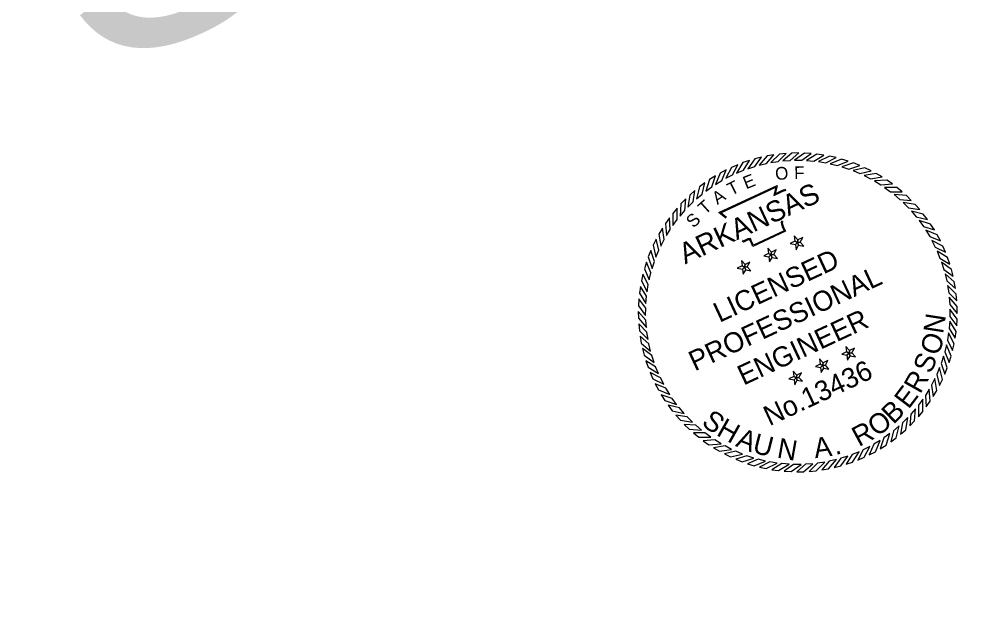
# Model space of a CAD drawing. Extents: x 757022 to 766943, y 1656388 to 1662319.
# Drawn here: x 758834 to 759548, y 1659146 to 1659585 of the extents above; entities that cross this region are included whole.
import ezdxf

# ---------------------------------------------------------------- set-up
doc = ezdxf.new("R2010")
doc.units = 0
doc.layers.add('1', color=7, linetype='Continuous')
doc.layers.add('G-ANNO-SYMB', color=7, linetype='Continuous')

msp = doc.modelspace()

# ---------------------------------------------------------------- linework, layer by layer
at = {"layer": 'G-ANNO-SYMB'}
for points in [[(759389.06, 1659481.46), (759384.09, 1659480.19), (759378.71, 1659472.79), (759383.99, 1659474.49)], [(759398.26, 1659483.23), (759393.2, 1659482.35), (759387.26, 1659475.4), (759392.66, 1659476.67)], [(759407.57, 1659484.27), (759402.46, 1659483.79), (759395.99, 1659477.33), (759401.47, 1659478.18)], [(759416.93, 1659484.58), (759411.8, 1659484.5), (759404.85, 1659478.56), (759410.37, 1659478.98)], [(759426.29, 1659484.16), (759421.17, 1659484.48), (759413.77, 1659479.1), (759419.31, 1659479.09)], [(759435.59, 1659483), (759430.51, 1659483.72), (759422.71, 1659478.94), (759428.24, 1659478.49)], [(759444.76, 1659481.11), (759439.76, 1659482.23), (759431.61, 1659478.08), (759437.08, 1659477.19)], [(759453.77, 1659478.51), (759448.86, 1659480.02), (759440.41, 1659476.52), (759445.8, 1659475.21)], [(759371.21, 1659475.79), (759366.5, 1659473.75), (759362.35, 1659465.6), (759367.3, 1659468.11)], [(759380.02, 1659478.98), (759375.17, 1659477.32), (759370.39, 1659469.52), (759375.52, 1659471.62)], [(759462.53, 1659475.21), (759457.76, 1659477.1), (759449.07, 1659474.28), (759454.33, 1659472.55)], [(759471.02, 1659471.24), (759466.41, 1659473.49), (759457.52, 1659471.36), (759462.63, 1659469.22)], [(759354.48, 1659467.39), (759350.14, 1659464.65), (759347.32, 1659455.95), (759351.81, 1659459.19)], [(759362.68, 1659471.92), (759358.14, 1659469.52), (759354.65, 1659461.07), (759359.38, 1659463.95)], [(759479.16, 1659466.61), (759474.75, 1659469.22), (759465.72, 1659467.79), (759470.65, 1659465.26)], [(759346.65, 1659462.24), (759342.55, 1659459.16), (759340.42, 1659450.27), (759344.64, 1659453.85)], [(759486.92, 1659461.35), (759482.72, 1659464.3), (759473.61, 1659463.59), (759478.32, 1659460.67)], [(759494.24, 1659455.5), (759490.29, 1659458.78), (759481.14, 1659458.78), (759485.62, 1659455.5)], [(759339.26, 1659456.48), (759335.41, 1659453.09), (759333.98, 1659444.06), (759337.91, 1659447.97)], [(759501.08, 1659449.1), (759497.4, 1659452.67), (759488.28, 1659453.39), (759492.48, 1659449.78)], [(759332.34, 1659450.17), (759328.77, 1659446.49), (759328.05, 1659437.37), (759331.66, 1659441.57)], [(759507.4, 1659442.18), (759504, 1659446.03), (759494.97, 1659447.46), (759498.88, 1659443.53)], [(759325.94, 1659443.33), (759322.67, 1659439.38), (759322.67, 1659430.23), (759325.94, 1659434.71)], [(759513.15, 1659434.79), (759510.07, 1659438.89), (759501.18, 1659441.03), (759504.76, 1659436.8)], [(759320.09, 1659436.01), (759317.14, 1659431.81), (759317.86, 1659422.69), (759320.77, 1659427.41)], [(759518.31, 1659426.97), (759515.56, 1659431.3), (759506.86, 1659434.13), (759510.1, 1659429.63)], [(759314.84, 1659428.25), (759312.22, 1659423.84), (759313.65, 1659414.8), (759316.19, 1659419.73)], [(759522.83, 1659418.76), (759520.43, 1659423.3), (759511.98, 1659426.8), (759514.86, 1659422.06)], [(759310.21, 1659420.11), (759307.95, 1659415.5), (759310.08, 1659406.61), (759312.22, 1659411.72)], [(759415.87, 1659417.55), (759414.05, 1659418.56), (759410.46, 1659416.88), (759414.35, 1659416.13)], [(759415.87, 1659417.55), (759416.27, 1659419.59), (759413.57, 1659422.49), (759414.05, 1659418.56)], [(759415.87, 1659417.55), (759414.35, 1659416.13), (759414.83, 1659412.19), (759416.75, 1659415.66)], [(759415.87, 1659417.55), (759417.94, 1659417.8), (759419.86, 1659421.27), (759416.27, 1659419.59)], [(759415.87, 1659417.55), (759416.75, 1659415.66), (759420.64, 1659414.9), (759417.94, 1659417.8)], [(759526.7, 1659410.23), (759524.66, 1659414.94), (759516.52, 1659419.09), (759519.02, 1659414.14)], [(759306.23, 1659411.62), (759304.34, 1659406.85), (759307.17, 1659398.16), (759308.9, 1659403.42)], [(759396.1, 1659408.33), (759394.28, 1659409.34), (759390.68, 1659407.66), (759394.57, 1659406.91)], [(759396.1, 1659408.33), (759396.49, 1659410.37), (759393.79, 1659413.27), (759394.28, 1659409.34)], [(759396.1, 1659408.33), (759398.17, 1659408.58), (759400.09, 1659412.05), (759396.49, 1659410.37)], [(759396.1, 1659408.33), (759396.98, 1659406.44), (759400.87, 1659405.68), (759398.17, 1659408.58)], [(759529.89, 1659401.42), (759528.23, 1659406.27), (759520.43, 1659411.05), (759522.53, 1659405.92)], [(759302.93, 1659402.85), (759301.42, 1659397.95), (759304.92, 1659389.5), (759306.23, 1659394.89)], [(759376.32, 1659399.11), (759376.72, 1659401.15), (759374.02, 1659404.05), (759374.5, 1659400.12)], [(759376.32, 1659399.11), (759378.39, 1659399.36), (759380.31, 1659402.83), (759376.72, 1659401.15)], [(759396.1, 1659408.33), (759394.57, 1659406.91), (759395.06, 1659402.97), (759396.98, 1659406.44)], [(759532.37, 1659392.39), (759531.1, 1659397.36), (759523.7, 1659402.73), (759525.4, 1659397.45)], [(759376.32, 1659399.11), (759374.5, 1659400.12), (759370.91, 1659398.44), (759374.8, 1659397.69)], [(759376.32, 1659399.11), (759374.8, 1659397.69), (759375.28, 1659393.75), (759377.2, 1659397.22)], [(759376.32, 1659399.11), (759377.2, 1659397.22), (759381.09, 1659396.46), (759378.39, 1659399.36)], [(759300.33, 1659393.85), (759299.21, 1659388.85), (759303.36, 1659380.7), (759304.25, 1659386.17)], [(759534.14, 1659383.19), (759533.26, 1659388.24), (759526.31, 1659394.18), (759527.59, 1659388.79)], [(759298.45, 1659384.68), (759297.72, 1659379.6), (759302.5, 1659371.8), (759302.95, 1659377.32)], [(759535.18, 1659373.88), (759534.7, 1659378.98), (759528.24, 1659385.45), (759529.09, 1659379.97)], [(759297.29, 1659375.38), (759296.96, 1659370.26), (759302.34, 1659362.86), (759302.36, 1659368.4)], [(759535.49, 1659364.51), (759535.42, 1659369.64), (759529.48, 1659376.6), (759529.89, 1659371.07)], [(759296.86, 1659366.02), (759296.94, 1659360.89), (759302.88, 1659353.94), (759302.46, 1659359.46)], [(759535.07, 1659355.15), (759535.39, 1659360.27), (759530.02, 1659367.67), (759530, 1659362.13)], [(759533.91, 1659345.86), (759534.63, 1659350.93), (759529.85, 1659358.73), (759529.4, 1659353.21)], [(759297.17, 1659356.66), (759297.65, 1659351.55), (759304.12, 1659345.08), (759303.27, 1659350.56)], [(759298.21, 1659347.35), (759299.09, 1659342.29), (759306.05, 1659336.35), (759304.77, 1659341.75)], [(759532.02, 1659336.68), (759533.14, 1659341.69), (759528.99, 1659349.83), (759528.11, 1659344.36)], [(759299.98, 1659338.15), (759301.25, 1659333.17), (759308.65, 1659327.8), (759306.96, 1659333.08)], [(759454.48, 1659334.74), (759454.88, 1659336.79), (759452.18, 1659339.69), (759452.66, 1659335.75)], [(759454.48, 1659334.74), (759456.55, 1659335), (759458.47, 1659338.46), (759454.88, 1659336.79)], [(759529.42, 1659327.68), (759530.93, 1659332.58), (759527.43, 1659341.03), (759526.12, 1659335.64)], [(759434.71, 1659325.52), (759435.11, 1659327.57), (759432.4, 1659330.47), (759432.89, 1659326.53)], [(759454.48, 1659334.74), (759452.66, 1659335.75), (759449.07, 1659334.08), (759452.96, 1659333.32)], [(759454.48, 1659334.74), (759452.96, 1659333.32), (759453.44, 1659329.39), (759455.36, 1659332.86)], [(759454.48, 1659334.74), (759455.36, 1659332.86), (759459.25, 1659332.1), (759456.55, 1659335)], [(759526.12, 1659318.91), (759528.01, 1659323.68), (759525.19, 1659332.38), (759523.46, 1659327.11)], [(759302.47, 1659329.11), (759304.13, 1659324.26), (759311.92, 1659319.48), (759309.82, 1659324.61)], [(759434.71, 1659325.52), (759432.89, 1659326.53), (759429.3, 1659324.86), (759433.19, 1659324.1)], [(759434.71, 1659325.52), (759433.19, 1659324.1), (759433.67, 1659320.17), (759435.59, 1659323.63)], [(759434.71, 1659325.52), (759436.78, 1659325.78), (759438.7, 1659329.24), (759435.11, 1659327.57)], [(759434.71, 1659325.52), (759435.59, 1659323.63), (759439.48, 1659322.88), (759436.78, 1659325.78)], [(759522.15, 1659310.43), (759524.41, 1659315.03), (759522.27, 1659323.92), (759520.13, 1659318.81)], [(759305.65, 1659320.3), (759307.69, 1659315.59), (759315.84, 1659311.44), (759313.34, 1659316.39)], [(759414.94, 1659316.3), (759413.11, 1659317.31), (759409.52, 1659315.64), (759413.41, 1659314.88)], [(759414.94, 1659316.3), (759415.33, 1659318.35), (759412.63, 1659321.25), (759413.11, 1659317.31)], [(759414.94, 1659316.3), (759413.41, 1659314.88), (759413.89, 1659310.95), (759415.82, 1659314.41)], [(759414.94, 1659316.3), (759417, 1659316.56), (759418.92, 1659320.02), (759415.33, 1659318.35)], [(759414.94, 1659316.3), (759415.82, 1659314.41), (759419.71, 1659313.66), (759417, 1659316.56)], [(759517.52, 1659302.28), (759520.13, 1659306.7), (759518.7, 1659315.73), (759516.17, 1659310.8)], [(759309.52, 1659311.77), (759311.92, 1659307.23), (759320.37, 1659303.73), (759317.49, 1659308.47)], [(759314.05, 1659303.57), (759316.8, 1659299.23), (759325.49, 1659296.41), (759322.25, 1659300.9)], [(759512.26, 1659294.52), (759515.22, 1659298.72), (759514.5, 1659307.84), (759511.59, 1659303.12)], [(759319.2, 1659295.74), (759322.28, 1659291.64), (759331.18, 1659289.5), (759327.59, 1659293.73)], [(759506.42, 1659287.2), (759509.69, 1659291.15), (759509.69, 1659300.3), (759506.42, 1659295.83)], [(759324.96, 1659288.35), (759328.35, 1659284.5), (759337.38, 1659283.07), (759333.48, 1659287)], [(759500.01, 1659280.36), (759503.59, 1659284.05), (759504.3, 1659293.16), (759500.69, 1659288.96)], [(759331.27, 1659281.43), (759334.96, 1659277.86), (759344.07, 1659277.14), (759339.87, 1659280.75)], [(759485.7, 1659268.29), (759489.8, 1659271.37), (759491.94, 1659280.26), (759487.71, 1659276.68)], [(759493.09, 1659274.05), (759496.94, 1659277.44), (759498.37, 1659286.47), (759494.44, 1659282.56)], [(759338.11, 1659275.03), (759342.07, 1659271.75), (759351.21, 1659271.75), (759346.74, 1659275.03)], [(759477.88, 1659263.14), (759482.21, 1659265.88), (759485.04, 1659274.58), (759480.54, 1659271.34)], [(759345.43, 1659269.18), (759349.63, 1659266.23), (759358.75, 1659266.95), (759354.03, 1659269.86)], [(759469.67, 1659258.61), (759474.21, 1659261.01), (759477.71, 1659269.46), (759472.97, 1659266.58)], [(759353.19, 1659263.93), (759357.61, 1659261.31), (759366.64, 1659262.74), (759361.71, 1659265.27)], [(759361.34, 1659259.3), (759365.94, 1659257.04), (759374.84, 1659259.17), (759369.72, 1659261.31)], [(759452.33, 1659251.56), (759457.19, 1659253.22), (759461.96, 1659261.01), (759456.84, 1659258.91)], [(759461.14, 1659254.74), (759465.85, 1659256.78), (759470, 1659264.93), (759465.06, 1659262.43)], [(759369.82, 1659255.32), (759374.59, 1659253.43), (759383.29, 1659256.26), (759378.02, 1659257.99)], [(759378.59, 1659252.02), (759383.49, 1659250.51), (759391.94, 1659254.01), (759386.56, 1659255.32)], [(759387.59, 1659249.42), (759392.6, 1659248.3), (759400.75, 1659252.45), (759395.27, 1659253.34)], [(759396.77, 1659247.54), (759401.85, 1659246.81), (759409.64, 1659251.59), (759404.12, 1659252.04)], [(759406.06, 1659246.38), (759411.18, 1659246.05), (759418.58, 1659251.43), (759413.04, 1659251.44)], [(759415.42, 1659245.95), (759420.55, 1659246.03), (759427.51, 1659251.97), (759421.98, 1659251.55)], [(759424.79, 1659246.26), (759429.9, 1659246.74), (759436.36, 1659253.2), (759430.88, 1659252.36)], [(759434.1, 1659247.3), (759439.15, 1659248.18), (759445.09, 1659255.13), (759439.7, 1659253.86)], [(759443.3, 1659249.07), (759448.27, 1659250.34), (759453.64, 1659257.74), (759448.37, 1659256.05)]]:
    msp.add_lwpolyline(points, close=True, dxfattribs=at)
for points in [[(759362.25, 1659435.67), (759357.19, 1659439.96), (759400.79, 1659460.32), (759399.28, 1659454.04), (759402.23, 1659455.46), (759404.69, 1659456.65), (759407.29, 1659457.53)], [(759362.75, 1659436.26), (759358.59, 1659439.77), (759399.68, 1659458.96), (759398.17, 1659452.66), (759402.56, 1659454.78), (759404.98, 1659455.94), (759407.53, 1659456.81)], [(759405, 1659433.35), (759404.54, 1659432.4), (759404.71, 1659431.38), (759405.52, 1659429), (759406.93, 1659425.99), (759382.58, 1659414.64), (759380.68, 1659418.71), (759380.26, 1659419.61), (759379.13, 1659419.45), (759375.67, 1659417.84), (759374.61, 1659418.49)], [(759404.32, 1659433.69), (759403.75, 1659432.51), (759403.97, 1659431.19), (759404.81, 1659428.72), (759405.92, 1659426.36), (759382.95, 1659415.65), (759381.37, 1659419.03), (759380.71, 1659420.44), (759378.91, 1659420.19), (759375.72, 1659418.7), (759375.02, 1659419.14)]]:
    msp.add_lwpolyline(points, dxfattribs=at)

# ---------------------------------------------------------------- texts
at = {"layer": '1'}
msp.add_text('PASTE SCALE = 1250', height=200, rotation=25, dxfattribs=at).set_placement((758026.33, 1659137.05))
at = {"layer": 'G-ANNO-SYMB'}
for s, height, rotation, p in [('O', 9.49, 6.2218, (759399.74, 1659464.11)), ('F', 9.49, 0.36282, (759413.45, 1659464.98)), ('E', 9.49, 21.67203, (759377.47, 1659457.32)), ('ARKANSAS', 15.494, 25, (759331.87, 1659401.16)), ('T', 9.49, 26.47887, (759366.34, 1659452.45)), ('A', 9.49, 33.67877, (759356.03, 1659445.55)), ('T', 9.49, 41.90148, (759346.85, 1659437.95)), ('S', 9.49, 44.77256, (759338.2, 1659427.94)), ('LICENSED', 15, 25, (759357.6, 1659357.36)), ('PROFESSIONAL', 15.0001, 25, (759339.07, 1659321.04)), ('ENGINEER', 15, 25, (759375.57, 1659310.38)), ('N', 15, 81.10067, (759524.81, 1659348.76)), ('O', 15, 69.77573, (759521.08, 1659332.12)), ('S', 15, 68.48784, (759515.94, 1659318.75)), ('No.13436', 14.941, 25, (759394.97, 1659279.97)), ('R', 15, 60.65967, (759507.75, 1659303.68)), ('E', 15, 52.83149, (759499.07, 1659292.3)), ('B', 15, 43.88501, (759487.63, 1659280.98)), ('S', 15, 323.16364, (759343.42, 1659281.47)), ('O', 15, 36.42961, (759475.34, 1659271.74)), ('H', 15, 330.61905, (759354.58, 1659273.7)), ('R', 15, 28.22866, (759461.85, 1659264.38)), ('A', 15, 338.44722, (759369, 1659265.32)), ('U', 15, 345.90262, (759381.61, 1659260.41)), ('N', 15, 349.93262, (759400.03, 1659256.67)), ('A', 15, 8.09908, (759429.16, 1659256.06)), ('.', 15, 16.30002, (759444.37, 1659258.33))]:
    msp.add_text(s, height=height, rotation=rotation, dxfattribs=at).set_placement(p)

doc.saveas('drawing.dxf')
